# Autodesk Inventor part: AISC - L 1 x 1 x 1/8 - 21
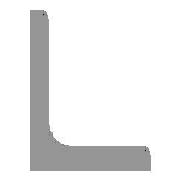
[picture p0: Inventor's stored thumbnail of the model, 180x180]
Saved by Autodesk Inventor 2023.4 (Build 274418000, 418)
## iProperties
Created: 2023-10
Part Number: AISC - L 1 x 1 x 1/8 - 21
Material: Steel, Mild
Description: Angle Steel
Document SubType Name: Modeling
Standard: AISC
Designer: Fred L.
Standards Organization: ANSI
Language: en-US
Size Designation: (L 1 x 1 x 1/8)
Categories: <MemberInstance><Categories><Category DisplayName="Structural Shapes" InternalName="089c4875-fa83-4c05-b084-43b9cc11f5ed" Mnemonic="GRDR"><CategoryParameter Dis
Stock Number: (L 1 x 1 x 1/8)
Mass: 638.766 g
Surface Area: 530.448 cm^2
Volume: 81.3714 cm^3
Density: 7.85 g/cm^3
Appearance: Semi-Polished
IsCustomPart: 1
G_L: 21.000 in
G_W: 1.000 in
G_H: 1.000 in
Mass: 1.41
SurfaceArea: 82.22
+586499EA-E712-4C99-99F7-965C7F7844D1+CUTDETAIL1: Corner Joint
+C1146D65-74C9-4788-BE2C-8E1DC69530BD+CUTDETAIL2: Corner Joint
_CCFamilyMember: 1
_CCFamilyDisplayName: ANSI L (Equal angles) - Angle Steel — Sizes in parentheses have been withdrawn
_FrameMemberDoc: Frame Member File
_Version: 25.0.0
_GetPNFromCC: 1
Author: Fred L.
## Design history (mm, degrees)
node "Start Plane"
node "End Plane"
sketch "Sketch"
  geometry: L1 (25.4, 0)-(0, 0); L2 (0, 0)-(0, 25.4); L3 (0, 25.4)-(1.651, 25.4); L4 (3.175, 23.876)-(3.175, 6.477); L5 (6.477, 3.175)-(23.876, 3.175); L6 (25.4, 1.651)-(25.4, 0); L7 (0, -11.041)-(0, 31.538); L8 (-11.041, 0)-(31.538, 0); L9 (0, 40.054)-(0, -19.557) reference; L10 (-19.557, 0)-(40.054, 0) reference; A1 r 3.302 centre (6.477, 6.477) between (3.175, 6.477) and (6.477, 3.175); A2 r 1.524 centre (1.651, 23.876) between (3.175, 23.876) and (1.651, 25.4); A3 r 1.524 centre (23.876, 1.651) between (25.4, 1.651) and (23.876, 3.175); 3 further points
  constraints: 16 end point, 6 point on circle, 6 point on line, 6 tangent, 4 parallel, 3 centre point, 2 collinear, 1 equal radius, 1 horizontal, 1 perpendicular
  dimensions: "d0" = 25.4 distance between parallel lines of L6 L2 (= G_H); "d1" = 25.4 distance between parallel lines of L3 L1 (= G_H); "d2" = 3.175 distance between parallel lines of L2 L4 (= G_T); "d3" = 3.175 distance between parallel lines of L1 L5 (= G_T); "d10" = 0 distance between parallel lines of L7 L2 (computed from ex); "d11" = 0 distance between parallel lines of L8 L1 (computed from d10); "d14" = 3.302 radius of A1 (= G_IR); "d15" = 1.524 radius of A2 (= G_ER)
extrude "Body" new body sketch "Sketch" stored distance "d4" = 533.4 (= G_L); taper "d5" = 0 deg
node "Driven Length"
  sketch "Sketch3"
    geometry: L1 (0, 0)-(10, 0) reference
    constraints: 2 end point, 1 horizontal
  workplane "Work Plane3"
workplane "Work Plane4"
split "Split1"
workplane "Work Plane5"
split "Split2"
body "Solid1"
sketch "Sketch4"
  geometry: L1 (-2, -12.7)-(12, -12.7) reference; L2 (-2, 520.7)-(12, 520.7) reference
  dimensions: "d17" = 533.4 distance between parallel lines of L1 L2 (derived)
other parameters: "G_H" = 25.4 [user parameter; used in 2 equation terms], "G_T" = 3.175 [user parameter; used in 2 equation terms], "G_ER" = 1.524 [user parameter; used in 1 equation term], "G_IR" = 3.302 [user parameter; used in 1 equation term], "G_L" = 533.4 (= d17) [user parameter; used in 1 equation term], "ex" = 0 [user parameter; used in 1 equation term], "G_OFFSET_START" = 12.7 [user parameter; used in 1 equation term], "G_OFFSET_END" = 12.7 [user parameter; used in 1 equation term], "d12" = -12.7 (= -G_OFFSET_START), "d13" = 520.7 (= G_OFFSET_END + B_L), "B_L" = 508 [user parameter; used in 1 equation term], "d16" = 90 deg, "MAS" = 0.11905 [user parameter]
